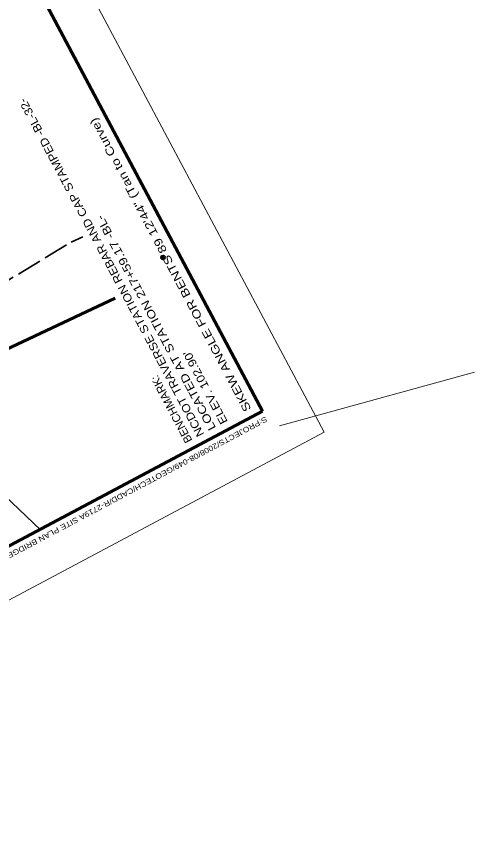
# Model space of a CAD drawing. Extents: x 2402199 to 2404507, y 568050 to 571478.
# Drawn here: x 2402674.4 to 2402829, y 570719 to 570995.3 of the extents above; entities that cross this region are included whole.
import ezdxf

# ---------------------------------------------------------------- set-up
doc = ezdxf.new("R2010")
doc.units = 0
doc.header["$LTSCALE"] = 1.4
doc.linetypes.add('LONG_DASHED', pattern=[7.5, 6, -1.5])
doc.linetypes.add('MEDIUM_DASHED', pattern=[4.5, 3, -1.5])
for name, color, linetype, lineweight in [('17', 7, 'MEDIUM_DASHED', 35), ('6', 7, 'Continuous', 35), ('63', 7, 'Continuous', 35)]:
    doc.layers.add(name, color=color, linetype=linetype, lineweight=lineweight)

msp = doc.modelspace()

# ---------------------------------------------------------------- linework, layer by layer
at = {"layer": '17', "linetype": 'LONG_DASHED'}
for p, q in [((2402692.803, 570919.098), (2402696.726, 570920.864)), ((2402639.183, 570886.623), (2402692.803, 570919.098))]:
    msp.add_line(p, q, dxfattribs=at)
at = {"layer": '17', "linetype": 'Continuous', "lineweight": 60}
msp.add_line((2402707.695, 570900.235), (2402626.394, 570862.088), dxfattribs=at)
at = {"layer": '6'}
msp.add_line((2402682.659, 570821.993), (2402635.453, 570866.339), dxfattribs=at)
at = {"layer": '63', "lineweight": 13}
for p, q in [((2402778.178, 570855.005), (2402538.748, 571305.309)), ((2402763.17, 570857.142), (2402828.95, 570875.226)), ((2402778.178, 570855.005), (2402486.806, 570700.08))]:
    msp.add_line(p, q, dxfattribs=at)
at = {"layer": '63', "lineweight": 60}
for p in [(2402531.138, 571287.671), (2402492.519, 570721.286)]:
    msp.add_line(p, (2402757.403, 570862.128), dxfattribs=at)
at = {"layer": '63', "lineweight": 53}
msp.add_circle((2402723.866, 570913.957), 0.551, dxfattribs=at)

# ---------------------------------------------------------------- texts
at = {"layer": '63'}
for s, height, rotation, width, p in [('NCDOT TRAVERSE STATION REBAR AND CAP STAMPED -BL-32-', 2.7, 118, 1.15, (2402737.792, 570854.375)), ('SKEW ANGLE FOR BENTS 89 12\'44" (Tan to Curve)', 2.7, 118, 1.3, (2402753.685, 570862.825)), ('LOCATED AT STATION 217+59.17 -BL-', 2.7, 118, 1.25, (2402741.765, 570856.488)), ("ELEV. 102.90'", 2.7, 118, 1.2, (2402745.739, 570858.6)), ('BENCHMARK: ', 2.7, 118, 1.05, (2402733.819, 570852.262)), ('S:PROJECTS/2008/08-049/GEOTECH/CADD/R-2719A SITE PLAN BRIDGE 198 LL.DGN', 1.8, 208, 1.2, (2402758.374, 570860.406))]:
    msp.add_text(s, height=height, rotation=rotation, dxfattribs=dict(at, width=width)).set_placement(p)

doc.saveas('drawing.dxf')
